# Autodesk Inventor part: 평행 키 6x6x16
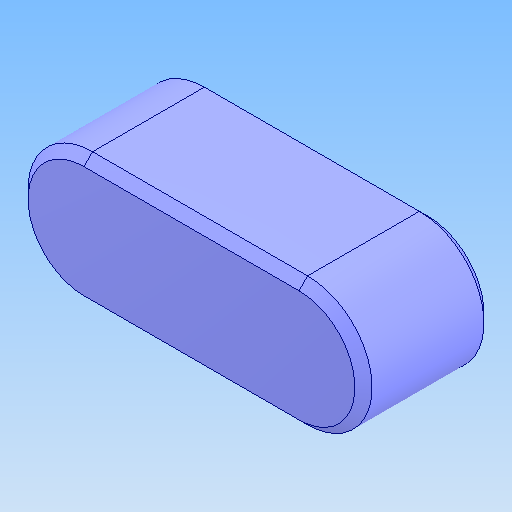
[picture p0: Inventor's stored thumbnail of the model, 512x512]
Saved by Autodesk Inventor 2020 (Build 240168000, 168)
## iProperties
Created: 2025-11
Part Number: 평행 키 6x6x16
Material: 강철, 연강
Description: 키 및 해당 키홈
Document SubType Name: Modeling
Designer: PC2-06
Density: 7.85 g/cm^3
Appearance: 기본값
Author: jhkim
Sending System: Autodesk Inventor 2026
Preprocessor: ST-DEVELOPER v20.1
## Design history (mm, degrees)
feature "Solid1"
node "솔리드1"
